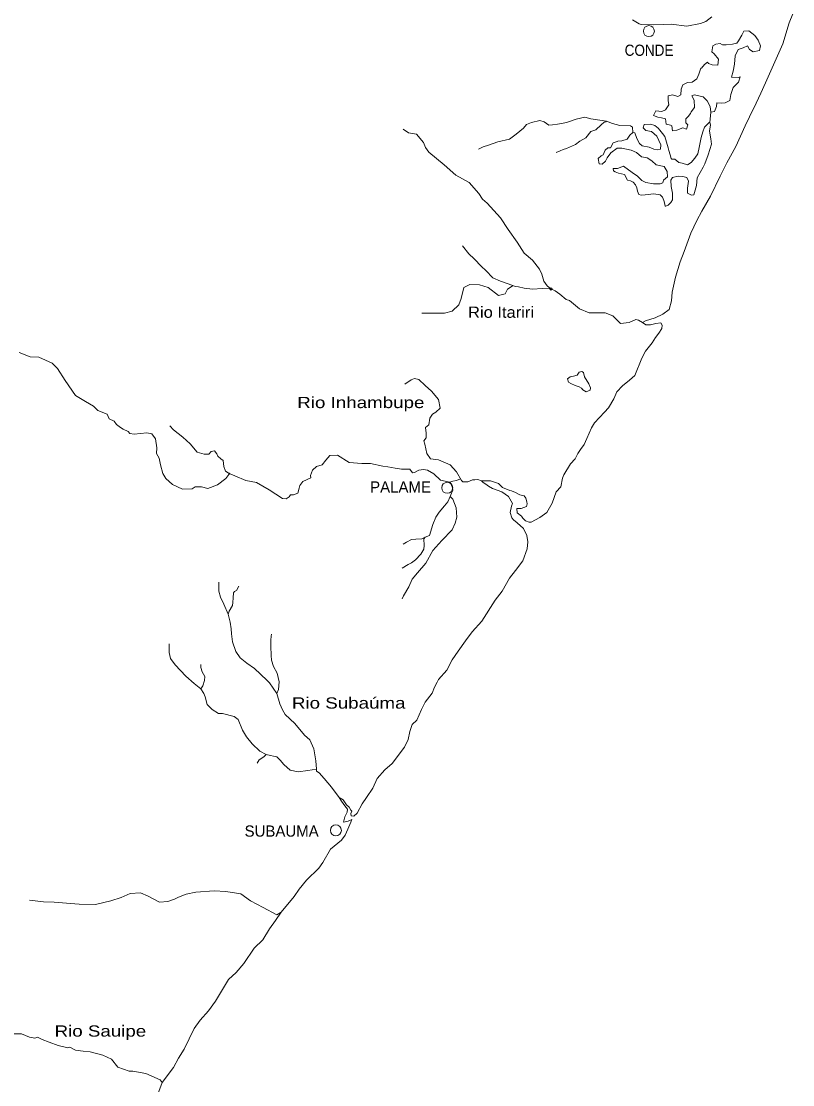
# Model space of a CAD drawing. Extents: x 47169 to 972804, y 7447977 to 9608469.
# Drawn here: x 613623 to 659584, y 8630617 to 8694007 of the extents above; entities that cross this region are included whole.
import ezdxf

# ---------------------------------------------------------------- set-up
doc = ezdxf.new("R2010")
doc.units = 0
doc.header["$LTSCALE"] = 270
doc.header["$PDMODE"] = 32
doc.header["$PDSIZE"] = 135
doc.layers.add('1', color=7, linetype='Continuous', lineweight=13)
doc.layers.add('2', color=7, linetype='Continuous', lineweight=13)
doc.layers.add('3', color=7, linetype='Continuous')

msp = doc.modelspace()

# ---------------------------------------------------------------- linework, layer by layer
at = {"layer": '1'}
for points in [[(654755, 8694273.7), (654404.8, 8693987.9), (654099.1, 8693867.8), (653281, 8693706), (652344.5, 8693832.3), (651864.9, 8693823.7), (651309, 8693793.2), (650557.3, 8693819.1), (650426.7, 8693852.9), (650035.5, 8694087.1)], [(655658.5, 8685574.9), (656186.4, 8686534.6), (656748.4, 8687770.5), (657012.7, 8688311.2), (657398.2, 8689116.7), (657684.6, 8689712.5), (657960.2, 8690330.5), (658434.3, 8691412), (658996.6, 8692670.1), (659373.6, 8693907), (659583.5, 8694459)], [(654635.8, 8687980.5), (654704.3, 8688588.5), (654662.4, 8688920.5), (654489.8, 8689264.3), (654240.4, 8689497.9), (653739.8, 8689622.1), (653576, 8689556.5), (653716.5, 8689312.5), (653725.1, 8688870), (653527.7, 8688616.6), (653494.5, 8688506.1), (653351.9, 8688329.9), (653220.5, 8688186.7), (653219.2, 8687943.4), (653338.5, 8687832.2), (653260.9, 8687567.1), (653032.5, 8687645.7), (652672.4, 8687525.8), (652421.6, 8687471.8), (652379.5, 8687781.7), (652292.5, 8687815.3), (652053.2, 8687882.9), (652011.1, 8688181.8), (651771.8, 8688260.4), (651554, 8688283.6), (651293, 8688384.4), (651425.2, 8688671.4), (651784.6, 8688636.4), (652002.9, 8688723.8), (652200.6, 8689032.5), (652169.2, 8689287.1), (652170.6, 8689563.6), (652421.4, 8689617.7), (652747.8, 8689527.5), (652922.7, 8689626.2), (652946.2, 8689969), (653045.5, 8690211.8), (653307.7, 8690365.4), (653591.1, 8690375), (653864.5, 8690583.8), (653996.6, 8690848.6), (654118.3, 8691201.9), (654151, 8691212.8), (654337.4, 8691433.1), (654501.6, 8691576.1), (654566.5, 8691498.3), (654784.1, 8691419.8), (655121.7, 8691384.8), (655156.2, 8691749.7), (654896.3, 8692060.7), (654766.2, 8692194.1), (654822.5, 8692547.8), (655008.2, 8692646.4), (655259, 8692678.3), (655400.3, 8692600.2), (655618.3, 8692610.1), (655988.9, 8692641.4), (656250.8, 8692706.4), (656360.4, 8692838.6), (656547.4, 8693169.5), (656679.4, 8693423.2), (656962.8, 8693432.8), (657321, 8693165.5), (657515.7, 8692876.9), (657655.6, 8692533.3), (657610.6, 8692257), (657228.8, 8692192.6), (657000.7, 8692326.5), (656881.9, 8692537.3), (656630.7, 8692416.9), (656325.1, 8692318.9), (656148.8, 8691943.7), (656113.6, 8691446.2), (656035.1, 8691026.2), (655935.2, 8690672.8), (656327.4, 8690648.7), (656447.5, 8690692.3), (656347.8, 8690383.1), (656041, 8690052.8), (655897.2, 8689633.2), (655841, 8689290.6), (655567.9, 8689148.2), (655339, 8689127.2), (655066.7, 8689150.8), (655043.7, 8688918.6), (654933.2, 8688620.5), (654704.3, 8688588.5)], [(650056.9, 8687373), (650047.6, 8687693.8), (649928.2, 8687782.9), (649285.5, 8687797.1), (648850.3, 8687920.9), (648491.3, 8688044.3), (647555.1, 8688192.7), (647206.9, 8688282.9), (646683.4, 8688163.7), (646170.5, 8687989.2), (646115.9, 8687967.4), (645570.7, 8687870.4), (645265.4, 8687827.7), (645047.5, 8687817.6), (644776, 8688007), (644525.9, 8688096.7), (644024.1, 8687966.3), (643718.5, 8687846.1), (643543.2, 8687636.8), (643105.7, 8687273.8), (642701.2, 8686977.1), (642014.2, 8686825.5), (641468.5, 8686628.9), (641141.2, 8686519.8), (640857.3, 8686377.4)], [(648491.3, 8688044.3), (648458.6, 8688022.4), (648349.5, 8688000.8), (648174.3, 8687824.7), (647856.9, 8687527.6), (647551.4, 8687440.6), (647255.4, 8687054.9), (646895, 8686857.5), (646632.5, 8686659.7), (646097.6, 8686430), (645912.1, 8686364.5), (645737.3, 8686276.9), (645497.2, 8686178.5)], [(651116.1, 8687865.5), (650723.9, 8687856.3), (650668.4, 8687657.5), (650831.1, 8687501.9), (651168.5, 8687444.9), (651494, 8687166.7), (651720.1, 8686634.7), (651708, 8686391.4), (651533.5, 8686348), (651315.7, 8686382.3), (651033, 8686494.3), (650608.6, 8686573.8), (650456.7, 8686718.4), (650294.8, 8687017.8), (650176.6, 8687350.2), (650056.9, 8687373), (649870.9, 8687208), (649728.1, 8686987.4), (649411.7, 8686878.4), (649161, 8686857.5), (649128.2, 8686835.6), (648877.2, 8686759.4), (648723.3, 8686461.5), (648570.8, 8686462.2), (648417.5, 8686319.2), (648285.5, 8686043.3), (648165.3, 8685977.5), (648001.1, 8685823.5), (648043.2, 8685513.6), (648228.2, 8685479.5), (648425.3, 8685677.6), (648535.2, 8685876.2), (648754.5, 8686173.7), (649126.3, 8686448.4), (649409.5, 8686436), (649964.5, 8686322.6), (650268.8, 8686177.3), (650572.6, 8685921.4), (650921, 8685875.4), (651181.6, 8685697.2), (651441.8, 8685441.4), (651920.6, 8685350.6), (652104.4, 8685062), (652113.6, 8684730.2), (651883.9, 8684532.2), (651839.5, 8684377.6), (651686.7, 8684323), (651294.6, 8684325), (650837.4, 8684393.7), (650598.3, 8684516.5), (650327.3, 8684783.3), (650012.4, 8684984), (649502.3, 8685373.7), (649153, 8685231.6), (648880.6, 8685232.9), (648912.6, 8685089), (649010.4, 8685033.2), (649195.1, 8684943.8), (649565.1, 8684864.5), (649737.8, 8684542.9), (649911.9, 8684497.8), (650085.8, 8684419.5), (650215.8, 8684264), (650302, 8684075.6), (650344.6, 8683876.2), (650409, 8683676.8), (650550.3, 8683631.9), (650790.2, 8683663.8), (651302.5, 8683727.7), (651683.4, 8683659.4), (651824.3, 8683514.9), (651910.5, 8683326.4), (651953.4, 8683193.5), (651985.1, 8682994.2), (652017.8, 8682994), (652170.5, 8683037.5), (652312.9, 8683202.7), (652411.7, 8683357.1), (652413.7, 8683755.3), (652350.4, 8684164.8), (652319.7, 8684541.1), (652418.5, 8684695.4), (652756.6, 8684782.2), (653028.8, 8684758.7), (653279.1, 8684691.1), (653365.2, 8684480.5), (653308.6, 8684060.5), (653307, 8683750.8), (653546.1, 8683650), (653687.8, 8683660.3), (653854.1, 8684223.6), (653889, 8684665.9), (654251.8, 8685305.6), (654350.9, 8685515.2), (654549.7, 8686045.2), (654749, 8686674.7), (654696.1, 8686995.7), (654633.1, 8687449.5), (654678.6, 8687836.4), (654635.8, 8687980.5), (654603.1, 8687980.6)], [(654603.1, 8687980.6), (654329.3, 8687694.4), (654218.9, 8687418.5), (654119.1, 8687076.1), (654018.1, 8686490.3), (653929, 8686114.7), (653742.5, 8685850.2), (653534.2, 8685596.8), (653315.6, 8685454.1), (653000.1, 8685544.2), (652804.3, 8685589.5), (652565.6, 8685778.7), (652391.2, 8685779.6), (652347.9, 8685824), (652272.8, 8686045.6), (652208.7, 8686311.4), (652155, 8686466.6), (651962.2, 8687131.2), (651832.5, 8687319.9), (651670, 8687508.7), (651561.7, 8687630.9), (651377.3, 8687797.8), (651116.1, 8687865.5)], [(636374.4, 8687570.3), (636689.3, 8687347.7), (637168.3, 8687268.1), (637580.1, 8686790.6), (637698.5, 8686480.4), (637904.3, 8686214), (638826.8, 8685457.7), (639521.1, 8684824), (640303.4, 8684389), (640877.7, 8683733.8), (641104.9, 8683411.9), (641387, 8683167.3), (642178.1, 8682289.8), (642632.3, 8681601.9), (643162.4, 8680836.2), (643584.1, 8680192.6), (644072.2, 8679770), (644494.4, 8679237), (644634.6, 8678937.7), (644752.3, 8678505.8), (644957.9, 8678228.3), (645174.9, 8678050.3)], [(652405.7, 8677859.7), (652595.4, 8678754.7), (652872.4, 8679671.4), (653115.1, 8680289.6), (653512.8, 8681371.5), (653865.2, 8682121.9), (654173, 8682684.5), (654689.6, 8683588.8), (655251.3, 8684769.5), (655658.5, 8685574.9)], [(650643.2, 8676054.5), (650393.4, 8676199.6), (650241.1, 8676233.5), (649837.3, 8676058.5), (649325.1, 8675983.7), (648869.9, 8676439.4), (648413.5, 8676629.7), (647465.9, 8676623.3), (646889.9, 8676869.5), (646293.4, 8677370.1), (646086.7, 8677426.4), (645707.1, 8677749), (645435.7, 8677938.4), (645174.9, 8678050.3), (644652.2, 8678074.9), (644074.9, 8678044.5), (643585, 8678091.1), (643236.9, 8678181.2), (643062.8, 8678204.2), (642573.5, 8678372.4), (642182, 8678507), (641714.6, 8678708.3), (641291.9, 8679141.6), (641031.7, 8679386.2), (640609.1, 8679852.7), (640294.6, 8680152.8), (639915.6, 8680630.2)], [(642933.8, 8678248.5), (642582.8, 8678040.5), (642450.8, 8677764.6), (642058.2, 8677666.9), (641439.7, 8678145.5), (640928.6, 8678302.7), (640351.4, 8678316.5), (639980.3, 8678141.2), (639835.6, 8677478.2), (639681.5, 8677113.9), (639287.6, 8676717.6), (638840.5, 8676598), (638306.9, 8676600.5), (637991.1, 8676601.9), (637740.6, 8676603.1), (637490.2, 8676604.2)], [(645771, 8666256.3), (645871.5, 8666764.7), (645937.8, 8666963.4), (646343.8, 8667625.1), (646617.5, 8667922.4), (646771.5, 8668242.4), (646946.8, 8668473.8), (647166, 8668771.4), (647320.2, 8669135.7), (647595.6, 8669764.8), (647782.1, 8670062.5), (648362.4, 8670701.2), (648603.2, 8670965.5), (648932.5, 8671494.8), (649108.8, 8671914.2), (649448.2, 8672277.6), (649863.6, 8672607.3), (650170, 8672893.4), (650599.9, 8673931), (650808.8, 8674339.2), (651203.4, 8674835), (651411.9, 8675154.7), (651609.3, 8675419.2), (651784.9, 8675694.8), (651796.7, 8675882.8), (651721.2, 8676027), (651427, 8675995.2), (651110.8, 8675908.4), (650991, 8675909), (650827.6, 8675909.8), (650643.2, 8676054.5), (650807.1, 8676153.2), (651396.1, 8676338.3), (651854.6, 8676557.2), (652215.4, 8676831.9), (652370.5, 8677351), (652405.7, 8677859.7)], [(626004.5, 8667043.2), (626048.2, 8667076.2), (625807.3, 8666756.4), (625315.8, 8666371.4), (624737.9, 8666152.6), (624368.2, 8666253.7), (623976.3, 8666255.3), (623801.7, 8666134.4), (623224.6, 8666114.6), (622627.1, 8666404.7), (622236.6, 8666749.1), (622063.7, 8667059.5), (621913.3, 8667557.8), (621827.9, 8667967.4), (621676.6, 8668244.5), (621688.9, 8668576.3), (621625.7, 8669107.4), (621409.2, 8669418), (621104.6, 8669474.5), (620734.3, 8669442.8), (620342.2, 8669389.1), (620092, 8669434.4), (619983.5, 8669545.4), (619701.1, 8669701.4), (619527.2, 8669790.6), (619288.5, 8669979.5), (619158.6, 8670168.1), (618865.2, 8670302), (618746.6, 8670590), (618192.1, 8670802.3), (617921, 8671068.8), (617443, 8671336.1), (616856.5, 8671703.4), (616228.5, 8672590.6), (615784.8, 8673300.2), (615470.3, 8673633.2), (614676.8, 8673979.1), (614154.3, 8674014.3), (613501.9, 8674271.1)], [(641047.8, 8666610.9), (640830.5, 8666700.4), (640645.3, 8666679.1), (640514.7, 8666679.8), (640220.2, 8666559.5), (639937.1, 8666549.7), (639850.4, 8666638.6), (639548, 8667148.8), (639179.8, 8667570.9), (638484.3, 8667861.7), (638005.6, 8667919.2), (637778.5, 8668252.1), (637672.1, 8668794.5), (637607.7, 8669005), (637739.2, 8669181.3), (637740.5, 8669457.9), (637709.3, 8669789.8), (637895.2, 8669943.8), (637962.3, 8670341.7), (638115.9, 8670584.3), (638312.4, 8670705.1), (638585.7, 8670947.2), (638479.3, 8671467.5), (638067.7, 8671956.1), (637677.3, 8672300.7), (637308.7, 8672656.4), (637058.6, 8672712.8), (636851.3, 8672636.3), (636480, 8672383.6)], [(622478.1, 8669900.3), (622694.9, 8669656.1), (623248.3, 8669222.4), (623693.1, 8668822.4), (624104.7, 8668323), (624517.9, 8668210.7), (624801, 8668209.5), (624943.1, 8668352.7), (625128.4, 8668407.2), (625280, 8668218.6), (625333.8, 8668074.6), (625507.4, 8667919), (625659.4, 8667818.8), (625690.6, 8667464.8), (625798.3, 8667198.9), (626004.5, 8667043.2), (626352.3, 8666920), (626993.4, 8666640.8), (627635.2, 8666505.3), (628395.3, 8666081.8), (629187.8, 8665558.5), (629394.5, 8665535.5), (629591, 8665667.4), (629667.8, 8665788.7), (629841.9, 8665787.9), (630103.6, 8665886.3), (630170.2, 8666173.6), (630225.3, 8666339.3), (630389.7, 8666570.8), (630880.5, 8666789.9), (630859.4, 8666933.8), (630969.6, 8667254.1), (631220.9, 8667463.1), (631548, 8667561.2), (631766.9, 8667836.8), (632007.7, 8668123.3), (632465.1, 8668143.4), (633159.9, 8667708.9), (633921.7, 8667650.2), (634422.4, 8667636.9), (635162.1, 8667489.8), (635455.9, 8667455.2), (635894.2, 8667361.5), (636282.7, 8667314.3)], [(636282.7, 8667314.3), (636772.5, 8667305.5), (636934.8, 8667094.6), (637043.8, 8667116.2), (637316.6, 8667258.7), (637589, 8667290.7), (637817.4, 8667245.4), (638197.4, 8667033.4), (638598.5, 8666644.5), (639153.1, 8666531.3), (639327.6, 8666585.8), (639545.5, 8666629), (639791.7, 8666737.7)], [(629101.8, 8640905), (629889.1, 8641841.7), (630184.7, 8642282.8), (630611.2, 8642800.8), (631354.2, 8643527.4), (631595, 8643858.2), (632044.6, 8644663.6), (632710.6, 8645191.5), (632918.7, 8645500.3), (633072.5, 8645842.5), (633248.5, 8646262), (633314.5, 8646427.6), (633096.4, 8646318), (632813.4, 8646275), (632901.8, 8646584.3), (633033.7, 8646871.3), (633056.2, 8647048.1), (632904.8, 8647247.9), (632710.2, 8647525.3), (632569.7, 8647736.1), (632797.6, 8647591.3), (632992.1, 8647302.8), (633154.6, 8647158.3), (633251.8, 8646991.9), (633316.8, 8646925.3), (633261.7, 8646781.8), (633271.9, 8646637.9), (633435.1, 8646626.1), (633631.8, 8646813.3), (633928, 8647364.9), (634190.8, 8647739.8), (634574.1, 8648291.1), (634827, 8648876.2), (635286.3, 8649382.8), (635712.4, 8649768), (636445.9, 8650738), (636665.7, 8651201.5), (636765.8, 8651665.6), (636920.1, 8652096.3), (637182.4, 8652338.4), (637457.4, 8652989.7), (637688, 8653420), (638104, 8653960), (638247.2, 8654324.4), (638400.9, 8654622.3), (638483.2, 8654765.7), (638970.1, 8655327.5), (639299.4, 8655934.3), (639650.2, 8656463.6), (640088.4, 8657080.9), (640482.7, 8657610), (641062.6, 8658248.8), (641863.1, 8659505.9), (642268.4, 8660034.9), (642707.5, 8660818.1), (643057.9, 8661258.9), (643496.2, 8661854), (643760.9, 8662560.7), (643806.5, 8662980.8), (643742.9, 8663346.1), (643538.1, 8663767.4), (643158.7, 8664101), (642952.8, 8664290.1), (642844.4, 8664401.2), (642748, 8664722.4), (642837, 8665109.1), (642892.1, 8665252.7), (642643.7, 8665674.2), (642253.2, 8665963.6), (641698.9, 8666154.3), (641460, 8666288.2), (641308.1, 8666410.5), (641145.3, 8666510.8), (641047.8, 8666610.9), (641200.3, 8666621.2), (641581.3, 8666608.3), (642059.5, 8666451.2), (642287, 8666217.8), (642732.5, 8666038.8), (642819.6, 8666027.3), (643069.4, 8665915.5), (643330.1, 8665781.5), (643591, 8665713.9), (643688.4, 8665580.7), (643741.8, 8665370.2), (643763, 8665248.5), (643718.6, 8665082.8), (643402.4, 8664973.7), (643206.4, 8664963.6), (643141.1, 8664963.9), (643172.5, 8664709.3), (643421.9, 8664509), (643497.5, 8664387), (643660.1, 8664231.3), (643888.3, 8664152.8), (643997.2, 8664152.3), (644521.1, 8664437.3), (644925.3, 8664723), (645243.7, 8665274.5), (645497.4, 8665959), (645771, 8666256.3)], [(639153.1, 8666531.3), (639239.7, 8666420.3), (639304, 8666187.7), (639325.1, 8666043.8), (639248.1, 8665878.2), (639181.8, 8665679.5), (639027.9, 8665359.4), (638841.8, 8665128), (638513.4, 8664742.4), (638316.1, 8664455.7), (638139.9, 8664014.1), (637951.8, 8663362.4), (637679.2, 8663253.1), (637482.8, 8663154.4), (637134.4, 8663145), (636873, 8663113), (636578.4, 8662948.4), (636371, 8662838.8)], [(639181.8, 8665679.5), (639333.5, 8665523.9), (639527, 8665003.1), (639568, 8664449.9), (639479.2, 8664085.3), (639292.3, 8663699.1), (638668.9, 8663060.4), (638143.6, 8662454.6), (637715.6, 8661704.4), (637223.1, 8661120.4), (636916.6, 8660745.8), (636707.7, 8660304.3), (636400.5, 8659763.8), (636312.6, 8659587.2)], [(637679.2, 8663253.1), (637613.5, 8663164.9), (637633.3, 8662755.6), (637599.7, 8662545.6), (637435.1, 8662247.7), (637106.9, 8661906.3), (636877.5, 8661719.3), (636681.2, 8661631.7), (636310.1, 8661412.2)], [(632569.7, 8647736.1), (632104.7, 8648357.6), (631661, 8648879.4), (631368.7, 8649201.5), (631216.8, 8649312.8), (631217.4, 8649434.4), (631176.1, 8649932.3), (631059.5, 8650629.7), (630822.5, 8651172.7), (630486.5, 8651461.8), (629923.7, 8652150), (629338.5, 8652683.5), (629187.4, 8652971.7), (629036.6, 8653326.3), (628854.3, 8653946.5), (628410.9, 8654567.8), (628259.2, 8654723.3), (627522.3, 8655423.3), (627055.7, 8655746.1), (626665.3, 8656057.4), (626405.7, 8656434.6), (626201.5, 8657021.7), (626149, 8657486.4), (626128.5, 8657785.1), (626065, 8658194.6), (625947.2, 8658659.7), (625699.4, 8659258), (625483.6, 8659679.2), (625398, 8660044.5), (625389.3, 8660564.4)], [(625947.2, 8658659.7), (626002.4, 8658847.5), (626199.8, 8659178.4), (626233.2, 8659366.3), (626256.1, 8659642.7), (626268.3, 8659941.3), (626323, 8660018.5), (626443, 8660073.3), (626585.6, 8660327.1)], [(628854.3, 8653946.5), (628942.4, 8654178.4), (628987.9, 8654631.7), (628870.5, 8655152), (628654.6, 8655551.1), (628536.5, 8655916.6), (628505.1, 8656204.3), (628496.6, 8656757.4), (628498.2, 8657122.4), (628510, 8657354.6), (628532.3, 8657465.1)], [(631217.4, 8649434.4), (630694.7, 8649348.3), (630128.6, 8649262.3), (629639.5, 8649364), (629271, 8649697.4), (629043.7, 8649963.9), (628848.7, 8650163.8), (628653.1, 8650208.9), (628479.1, 8650231.8), (628218.3, 8650310.4), (627838.3, 8650500.1), (627383.2, 8650933.4), (627047.7, 8651355.1), (626799.1, 8651743.3), (626540.7, 8652385.9), (626313, 8652563.8), (625617.4, 8652743.8), (625378, 8652744.8), (624998.2, 8652989.8), (624694.8, 8653289.7), (624577, 8653743.6), (624501.7, 8653943), (624317.9, 8654220.3), (623927.4, 8654531.6), (623417.8, 8654976.2), (622800.3, 8655642.4), (622519, 8656019.6), (622433.4, 8656384.9), (622435.5, 8656893.7)], [(624317.9, 8654220.3), (624438.2, 8654385.7), (624548.4, 8654706), (624549.5, 8654949.3), (624398.3, 8655226.5), (624312.3, 8655492.3), (624313, 8655658.2)], [(628218.3, 8650310.4), (628065.3, 8650156.2), (627792.6, 8649991.5), (627672, 8649792.9)], [(629101.8, 8640905), (628850.9, 8640751.3), (628037.1, 8641186.2), (627288.3, 8641587.7), (626702.7, 8641988.4), (625811.4, 8642136), (625115.4, 8642172.2), (624016.4, 8642088.4), (623450.3, 8641969.1), (622992.8, 8641805.1), (622753, 8641684.5), (622349.9, 8641531.3), (621860.3, 8641500.2), (621176.6, 8641856.9), (620720.5, 8642046.8), (620111.3, 8642016.2), (619566.5, 8641775.1), (618967.4, 8641578.4), (618042, 8641361), (617063.2, 8641376), (616312.9, 8641434.2), (615584.4, 8641492.4), (614953.7, 8641517), (614105.7, 8641608.8)], [(621692.2, 8629887.5), (622022, 8630748.8), (622689, 8631641.9), (622985, 8632204.7), (623324.3, 8632734.2), (623927.6, 8633959.3), (624277.7, 8634455.6), (624780.3, 8635017.5), (625196, 8635590.9), (625962.8, 8636881.6), (626432.3, 8637311), (626880.5, 8637851), (627493.5, 8638755.3), (628017.8, 8639261.8), (628401.3, 8639912.7), (628762.4, 8640408.8), (629101.8, 8640905)], [(622022, 8630748.8), (621903, 8630904.2), (621045.7, 8631283.8), (620274.2, 8631419.7), (620046, 8631431.7), (619372.8, 8631655.7), (618994.2, 8632132.9), (618473.2, 8632378.3), (617723.8, 8632580.4), (617310.8, 8632626.3), (616854.3, 8632683.5), (616507.1, 8632850.8), (616387.3, 8632818.1), (615822.5, 8632964.1), (615279.6, 8633154.3), (614867, 8633310.8), (614595.7, 8633455.6), (614421.5, 8633389.9), (614106.4, 8633457.5), (613639.7, 8633658.5), (613139.5, 8633660.4)]]:
    msp.add_lwpolyline(points, dxfattribs=at)
msp.add_lwpolyline([(646856.3, 8672224), (646617.2, 8672302.6), (646367.2, 8672414.4), (646226.1, 8672503.6), (646172.7, 8672703), (646325.6, 8672812.8), (646521.8, 8672856.1), (646750.8, 8672921.4), (646860.6, 8673086.7), (647013.2, 8673130.2), (647111, 8673074.4), (647175, 8672819.7), (647434.2, 8672387.1), (647542.1, 8672165.3), (647508.7, 8672021.7), (647279.5, 8671912.2), (647084.1, 8672045.9), (646997.5, 8672145.9)], close=True, dxfattribs=at)
msp.add_point((645174.9, 8678050.3), dxfattribs=at)
at = {"layer": '2'}
for centre, radius in [((651013, 8693418.6), 326.9), ((638999.2, 8666200.2), 328.6), ((632365.1, 8645779.3), 326.4)]:
    msp.add_circle(centre, radius, dxfattribs=at)

# ---------------------------------------------------------------- texts
at = {"layer": '3'}
for s, height, width, p in [('CONDE', 668.8, 0.9, (649571.3, 8691945.2)), ('Rio Itariri', 668.4, 1.1, (640240, 8676331.2)), ('Rio Inhambupe', 668.3, 1.25, (630065.3, 8670949.5)), ('Rio Subaúma', 667.9, 1.25, (629747.7, 8653038.2)), ('Rio Sauipe', 667.4, 1.25, (615607.1, 8633484.8))]:
    msp.add_text(s, height=height, dxfattribs=dict(at, width=width)).set_placement(p)
for s, height, p in [('PALAME', 668.2, (634404.9, 8665913.1)), ('SUBAUMA', 667.7, (626926.7, 8645403))]:
    msp.add_text(s, height=height, dxfattribs=at).set_placement(p)

doc.saveas('drawing.dxf')
